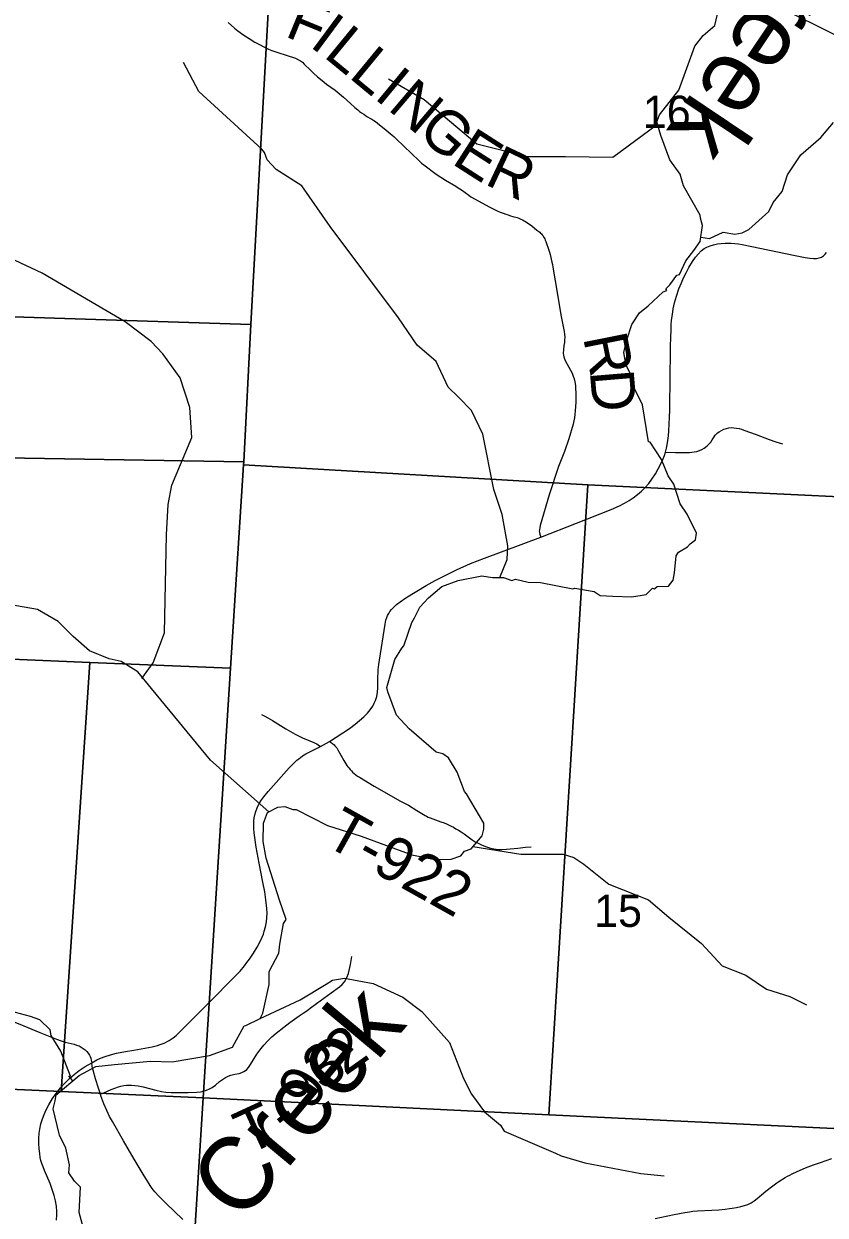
# Model space of a CAD drawing. Extents: x -2.1 to 31.9, y 6.3 to 28.3.
# Drawn here: x 2.076 to 3.117, y 21.978 to 23.525 of the extents above; entities that cross this region are included whole.
import ezdxf

# ---------------------------------------------------------------- set-up
doc = ezdxf.new("R2010")
doc.units = 0
for name, color, linetype in [('GM_X_County_Road', 7, 'Continuous'), ('GM_X_Minor_River', 7, 'Continuous'), ('GM_X_Minor_River_Text', 7, 'Continuous'), ('GM_X_Section', 7, 'Continuous'), ('GM_X_Section_Text', 7, 'Continuous'), ('GM_X_State_Route', 7, 'Continuous'), ('GM_X_Township_Road', 7, 'Continuous'), ('GM_X_Township_Road_Text', 7, 'Continuous'), ('TX_P_1', 7, 'Continuous')]:
    doc.layers.add(name, color=color, linetype=linetype)

msp = doc.modelspace()

# ---------------------------------------------------------------- linework, layer by layer
at = {"layer": 'GM_X_County_Road'}
for points in [[(2.0642, 22.2285), (2.0759, 22.2238), (2.0964, 22.2151), (2.1181, 22.2065), (2.1243, 22.2044), (2.1268, 22.2035), (2.1295, 22.2027), (2.1412, 22.1998), (2.1444, 22.1988), (2.1475, 22.1977), (2.1505, 22.1963), (2.1531, 22.1945), (2.1555, 22.1926), (2.1577, 22.1904), (2.1595, 22.1881), (2.1609, 22.1859), (2.1619, 22.184), (2.1627, 22.1818), (2.1634, 22.1794), (2.164, 22.1758)], [(2.8958, 21.9737), (2.9205, 21.9787), (2.9344, 21.9814), (2.9405, 21.9824), (2.9448, 21.9829), (2.9509, 21.9835), (2.9695, 21.9842), (2.9788, 21.9848), (2.9869, 21.9858), (2.9924, 21.9865), (2.9961, 21.987), (3.0018, 21.988), (3.0074, 21.989), (3.0122, 21.9903), (3.0163, 21.9919), (3.0208, 21.9941), (3.0246, 21.9964), (3.0286, 21.9994), (3.0398, 22.0091), (3.0471, 22.0149), (3.0541, 22.0198), (3.0566, 22.0215), (3.0649, 22.0266), (3.0681, 22.0284), (3.0708, 22.0298), (3.074, 22.0314), (3.0806, 22.0348), (3.0914, 22.0394), (3.1018, 22.0433), (3.1106, 22.0464), (3.1254, 22.0513)]]:
    msp.add_lwpolyline(points, dxfattribs=at)
at = {"layer": 'GM_X_Minor_River'}
for points in [[(2.8588, 23.1122), (2.8592, 23.1149), (2.8656, 23.1347), (2.8758, 23.1499), (2.8867, 23.1591), (2.9064, 23.1773), (2.9113, 23.1789), (2.9098, 23.1812), (2.9151, 23.1861), (2.9241, 23.199), (2.9275, 23.1998), (2.9358, 23.2173), (2.9464, 23.231), (2.9543, 23.2424), (2.9577, 23.2634), (2.955, 23.2728), (2.9543, 23.2766), (2.9327, 23.315), (2.9285, 23.3302), (2.9149, 23.3488), (2.9032, 23.3803), (2.8982, 23.3981), (2.9016, 23.4069), (2.9269, 23.4392), (2.9477, 23.4963), (2.9582, 23.51), (2.9737, 23.5233), (2.9771, 23.5378)], [(2.6941, 22.8063), (2.7036, 22.8293), (2.7046, 22.8472), (2.6971, 22.888), (2.6864, 22.9206), (2.6723, 22.9925), (2.6574, 23.0229), (2.6405, 23.0402), (2.6269, 23.0535), (2.6117, 23.0867), (2.5866, 23.108), (2.5627, 23.1433), (2.4737, 23.2619), (2.4371, 23.3147), (2.4038, 23.3359), (2.3921, 23.3488), (2.3886, 23.358), (2.3849, 23.3627), (2.3033, 23.4374), (2.2833, 23.4749)], [(2.8992, 23.3946), (2.8408, 23.3516), (2.7796, 23.3524), (2.7301, 23.3525), (2.6645, 23.369), (2.5959, 23.4266), (2.5495, 23.4535)], [(2.2292, 22.675), (2.2438, 22.6952), (2.2584, 22.7344), (2.261, 22.8616), (2.2631, 22.9011), (2.2682, 22.9261), (2.294, 22.9878), (2.2915, 23.0269), (2.2788, 23.0655), (2.2562, 23.0966), (2.2413, 23.1128), (2.2074, 23.1381), (2.0996, 23.2016), (2.0573, 23.2215), (1.9474, 23.2691), (1.86, 23.3382), (1.844, 23.3483), (1.765, 23.3707), (1.749, 23.3785), (1.7173, 23.4027)], [(2.9553, 23.2483), (2.9664, 23.2463), (2.9842, 23.2547), (2.9993, 23.2521), (3.0091, 23.254), (3.0178, 23.2582), (3.0435, 23.2814), (3.0495, 23.2932), (3.0609, 23.3077), (3.068, 23.329), (3.0854, 23.3552), (3.1111, 23.3777), (3.1277, 23.3971)], [(2.5694, 22.7172), (2.5798, 22.7475), (2.5832, 22.7536), (2.5903, 22.7677), (2.6017, 22.7799), (2.6187, 22.7943), (2.6402, 22.8024), (2.6708, 22.8081), (2.6848, 22.8063), (2.6988, 22.8063), (2.7098, 22.8022), (2.7147, 22.8041), (2.7309, 22.7999), (2.7472, 22.7996), (2.7892, 22.7913), (2.7918, 22.7921), (2.8168, 22.788), (2.8247, 22.7827), (2.841, 22.7819), (2.8659, 22.7809), (2.8844, 22.7839), (2.8927, 22.7923), (2.895, 22.7916), (2.8988, 22.7946), (2.9135, 22.7947), (2.9192, 22.8027), (2.9211, 22.8122), (2.9233, 22.8342), (2.9263, 22.8392), (2.938, 22.846), (2.9414, 22.8498), (2.9482, 22.8552), (2.9497, 22.8639), (2.9376, 22.8882), (2.9285, 22.9019), (2.9202, 22.9273), (2.913, 22.9383), (2.9043, 22.9592), (2.8895, 22.982), (2.8873, 22.9823), (2.8797, 23.0302), (2.8649, 23.0602), (2.863, 23.072), (2.8577, 23.083), (2.8554, 23.0986), (2.8588, 23.1122)], [(2.3942, 22.5017), (2.3181, 22.569), (2.2416, 22.6621), (2.2241, 22.6836), (2.2022, 22.6972), (2.1868, 22.7003), (2.161, 22.711), (2.1401, 22.7295), (2.1206, 22.7488), (2.0935, 22.7644), (2.0465, 22.7727)], [(2.347, 22.1959), (2.3621, 22.2236), (2.3644, 22.2244), (2.3829, 22.2332), (2.3863, 22.2404), (2.3946, 22.2777), (2.3946, 22.2944), (2.407, 22.3184), (2.4085, 22.3298), (2.413, 22.3568), (2.4164, 22.3621), (2.4081, 22.3872), (2.3907, 22.4415), (2.3869, 22.4631), (2.3872, 22.4871), (2.3925, 22.5008), (2.4057, 22.508), (2.4148, 22.5088), (2.4254, 22.505), (2.4295, 22.505), (2.4704, 22.4842), (2.5142, 22.4703), (2.58, 22.4461), (2.6099, 22.4397), (2.6311, 22.4402), (2.6436, 22.4444), (2.6481, 22.4508), (2.6568, 22.4535), (2.6711, 22.4707), (2.6734, 22.4794), (2.6734, 22.487), (2.6507, 22.525), (2.6484, 22.528), (2.6389, 22.5534), (2.6276, 22.572), (2.62, 22.5773), (2.6117, 22.5792), (2.5765, 22.6095), (2.5598, 22.6274), (2.5489, 22.6577), (2.5473, 22.6634), (2.5579, 22.6996), (2.567, 22.7144), (2.5694, 22.7172)], [(2.6593, 22.4566), (2.7215, 22.4468), (2.7763, 22.4466), (2.7905, 22.4423), (2.8035, 22.4336), (2.8356, 22.4079), (2.8872, 22.3876), (2.9137, 22.3651), (2.9561, 22.3307), (2.9832, 22.3018), (3.0138, 22.2898), (3.0405, 22.2715), (3.0708, 22.2621), (3.0928, 22.2512)], [(2.3829, 22.2332), (2.4346, 22.2577), (2.4684, 22.2779), (2.4769, 22.283), (2.4925, 22.2859), (2.5297, 22.279), (2.5681, 22.2611), (2.5928, 22.2424), (2.629, 22.2022), (2.6469, 22.1553), (2.6576, 22.1352), (2.6743, 22.1119), (2.695, 22.0949), (2.7, 22.0872), (2.7664, 22.0585), (2.7739, 22.0548), (2.8046, 22.0459), (2.8775, 22.0318), (2.9077, 22.0288)], [(2.1395, 22.1522), (2.1343, 22.1584), (2.1365, 22.1584), (2.124, 22.1907), (2.1115, 22.2112), (2.11, 22.2184), (2.0964, 22.2317), (2.0843, 22.2358), (2.0385, 22.2479)], [(2.1694, 22.1711), (2.1936, 22.1734), (2.2405, 22.1781), (2.2684, 22.177), (2.3168, 22.1851), (2.347, 22.1959)], [(2.1541, 21.9574), (2.1476, 21.9814), (2.1495, 22.0144), (2.1416, 22.022), (2.1344, 22.033), (2.1351, 22.0433), (2.1302, 22.0649), (2.1222, 22.0816), (2.1215, 22.0835), (2.1139, 22.1162), (2.1165, 22.1265), (2.1176, 22.1341), (2.1479, 22.1592), (2.1694, 22.1711)]]:
    msp.add_lwpolyline(points, dxfattribs=at)
at = {"layer": 'GM_X_Section'}
for points in [[(2.4194, 23.947), (3.4671, 23.8965), (3.4412, 23.4777), (3.416, 23.0562), (3.4084, 22.8979), (2.8085, 22.9264), (2.3612, 22.9526), (2.3614, 22.9562), (2.3709, 23.1348), (2.3938, 23.5483)], [(1.3641, 23.5904), (2.3938, 23.5483), (2.3709, 23.1348), (1.3376, 23.1681)], [(1.3376, 23.1681), (2.3709, 23.1348), (2.3614, 22.9562), (1.3254, 22.9735)], [(2.3614, 22.9562), (2.3612, 22.9526), (2.3441, 22.6882), (2.1616, 22.6959), (1.3796, 22.7292), (1.3102, 22.7307), (1.3254, 22.9735)], [(2.8085, 22.9264), (2.758, 22.1083), (2.3089, 22.1301), (2.3441, 22.6882), (2.3612, 22.9526)], [(3.4084, 22.8979), (3.3918, 22.6602), (3.3206, 22.6609), (3.2816, 22.083), (2.758, 22.1083), (2.8085, 22.9264)], [(2.1616, 22.6959), (2.1245, 22.1384), (1.3414, 22.174), (1.3796, 22.7292)], [(2.3441, 22.6882), (2.3089, 22.1301), (2.1245, 22.1384), (2.1616, 22.6959)], [(1.3414, 22.174), (2.1245, 22.1384), (2.3089, 22.1301), (2.2923, 21.8673), (1.3233, 21.9111)], [(2.3089, 22.1301), (2.758, 22.1083), (3.2816, 22.083), (3.264, 21.8222), (2.2923, 21.8673)]]:
    msp.add_lwpolyline(points, close=True, dxfattribs=at)
at = {"layer": 'GM_X_State_Route'}
for points in [[(2.2187, 22.1924), (2.2427, 22.1966), (2.2494, 22.1983), (2.253, 22.1994), (2.2582, 22.2015), (2.2644, 22.2046), (2.2697, 22.2081), (2.2736, 22.2112), (2.2791, 22.2163), (2.3187, 22.2563), (2.3474, 22.2852), (2.3524, 22.2903), (2.3569, 22.295), (2.3625, 22.3018), (2.3657, 22.306), (2.3688, 22.3103), (2.3741, 22.318), (2.379, 22.326), (2.3826, 22.3326), (2.3855, 22.3389), (2.387, 22.343), (2.3882, 22.3466), (2.3898, 22.3526), (2.391, 22.3588), (2.3916, 22.3644), (2.3918, 22.3701), (2.3915, 22.3764), (2.3903, 22.3875), (2.3889, 22.398), (2.3864, 22.4102), (2.3816, 22.435), (2.3778, 22.4558), (2.3768, 22.4621), (2.3758, 22.4684), (2.3751, 22.4746), (2.3748, 22.4795), (2.3745, 22.485), (2.3746, 22.4899), (2.3749, 22.494), (2.3758, 22.498), (2.3772, 22.5024), (2.3791, 22.507), (2.3813, 22.5116), (2.3839, 22.5159), (2.3878, 22.5214), (2.3932, 22.5281), (2.4206, 22.5589), (2.4243, 22.5628), (2.4278, 22.5663), (2.4305, 22.5688), (2.4329, 22.5708), (2.4352, 22.5725), (2.4379, 22.5744), (2.44, 22.5758), (2.4422, 22.577), (2.4446, 22.5783), (2.4472, 22.5796), (2.4613, 22.5867), (2.4731, 22.5932), (2.4988, 22.6101), (2.5061, 22.6155), (2.5121, 22.6204), (2.5175, 22.6252), (2.5222, 22.63), (2.5258, 22.6342), (2.529, 22.6389), (2.5311, 22.6428), (2.5326, 22.6462), (2.5342, 22.6517), (2.5351, 22.6572), (2.5355, 22.6628), (2.5359, 22.6777), (2.5361, 22.682), (2.5363, 22.6863), (2.5369, 22.6931), (2.5377, 22.6986), (2.5454, 22.7457), (2.5463, 22.7505), (2.5472, 22.754), (2.5483, 22.7568), (2.5498, 22.7595), (2.5514, 22.7619), (2.5536, 22.7644), (2.556, 22.7671), (2.56, 22.7709), (2.5648, 22.7747), (2.572, 22.7796), (2.5984, 22.7958), (2.6103, 22.8024), (2.6247, 22.8097), (2.6381, 22.8161), (2.6563, 22.8242), (2.6741, 22.8313), (2.7474, 22.8584), (2.7937, 22.8767), (2.8387, 22.8946), (2.8496, 22.8994), (2.8563, 22.9028), (2.8622, 22.9062), (2.8674, 22.9097), (2.8729, 22.9139), (2.8782, 22.9183), (2.8831, 22.9232), (2.8876, 22.9284), (2.8918, 22.9339), (2.8963, 22.9407), (2.9, 22.9472), (2.9034, 22.9539), (2.906, 22.9596), (2.908, 22.9647), (2.9093, 22.9689), (2.9107, 22.9742), (2.9116, 22.9785), (2.9126, 22.9842), (2.9133, 22.9903), (2.9138, 22.9965), (2.9144, 23.0055), (2.9148, 23.0148), (2.915, 23.0232), (2.9152, 23.0338), (2.9154, 23.0588), (2.9159, 23.1068), (2.9162, 23.1178), (2.9166, 23.1277), (2.9169, 23.1344), (2.9174, 23.1405), (2.9184, 23.1477), (2.9195, 23.1553), (2.9212, 23.1631), (2.9236, 23.1716), (2.9268, 23.1809), (2.93, 23.189), (2.9328, 23.1954), (2.9361, 23.2019), (2.9396, 23.2086), (2.9444, 23.2164), (2.9486, 23.2223), (2.952, 23.2263), (2.9559, 23.2303), (2.9598, 23.2333), (2.9633, 23.2354), (2.9673, 23.237), (2.9719, 23.2383), (2.9768, 23.2394), (2.9816, 23.2401), (2.987, 23.2405), (2.9905, 23.2406), (2.9947, 23.2405), (2.9994, 23.24), (3.0042, 23.2394), (3.0091, 23.2386), (3.078, 23.2243), (3.0907, 23.2217), (3.097, 23.2207), (3.1016, 23.2203), (3.1055, 23.2205), (3.1089, 23.2212), (3.1119, 23.2223), (3.1146, 23.224), (3.1168, 23.2262), (3.1184, 23.2282)], [(2.164, 22.1758), (2.1706, 22.1796), (2.1756, 22.1819), (2.1814, 22.184), (2.1885, 22.1861), (2.1962, 22.1881), (2.2078, 22.1905), (2.2187, 22.1924)], [(2.1183, 21.9713), (2.1187, 21.9782), (2.1186, 21.9826), (2.1181, 21.9894), (2.117, 21.9963), (2.1152, 22.0036), (2.1127, 22.0113), (2.1098, 22.0189), (2.1026, 22.0361), (2.1008, 22.0408), (2.0992, 22.0449), (2.0979, 22.0491), (2.0971, 22.0529), (2.0964, 22.0579), (2.0957, 22.0641), (2.0952, 22.0708), (2.0953, 22.0776), (2.0958, 22.0844), (2.0965, 22.0898), (2.098, 22.0965), (2.0999, 22.1029), (2.1021, 22.1087), (2.1048, 22.1149), (2.1083, 22.1214), (2.1132, 22.1293), (2.1179, 22.136), (2.1236, 22.1433), (2.1292, 22.1495), (2.1353, 22.1555), (2.1412, 22.1607), (2.1479, 22.1657), (2.1557, 22.1709), (2.164, 22.1758)], [(2.2321, 22.0291), (2.219, 22.0508), (2.2055, 22.0743), (2.1909, 22.0996), (2.1873, 22.106), (2.1835, 22.1138), (2.1798, 22.1223), (2.1759, 22.1327), (2.1752, 22.1349), (2.1727, 22.1427), (2.1691, 22.1548), (2.1658, 22.1663), (2.1651, 22.1689), (2.1646, 22.1713), (2.164, 22.1758)], [(2.2824, 21.9724), (2.2603, 21.9933), (2.2514, 22.0025), (2.246, 22.0084), (2.2427, 22.0126), (2.2401, 22.0163), (2.2351, 22.0241), (2.2321, 22.0291)]]:
    msp.add_lwpolyline(points, dxfattribs=at)
at = {"layer": 'GM_X_Township_Road'}
for points in [[(2.3411, 23.5269), (2.3494, 23.5197), (2.3537, 23.5163), (2.3618, 23.5105), (2.3687, 23.5061), (2.3759, 23.5016), (2.3938, 23.4925), (2.3978, 23.4907), (2.4019, 23.4892), (2.4206, 23.4834), (2.425, 23.4819), (2.4287, 23.4805), (2.4326, 23.4786), (2.4353, 23.4771), (2.4377, 23.4753), (2.4402, 23.4731), (2.4482, 23.4649), (2.4522, 23.4613), (2.4575, 23.4565), (2.4635, 23.4516), (2.4691, 23.4471), (2.4804, 23.439), (2.4911, 23.4302), (2.5, 23.4217), (2.506, 23.4164), (2.5096, 23.4134), (2.512, 23.4116), (2.5146, 23.4097), (2.5173, 23.4078), (2.5197, 23.4062), (2.5222, 23.4046), (2.5252, 23.4028), (2.5279, 23.4014), (2.5304, 23.3999), (2.5326, 23.3984), (2.5353, 23.3963), (2.5467, 23.387), (2.5542, 23.3808), (2.5565, 23.3788), (2.5594, 23.3761), (2.5893, 23.3472), (2.5907, 23.3459), (2.5925, 23.3444), (2.5954, 23.342), (2.6116, 23.3302), (2.6236, 23.3223), (2.637, 23.3143), (2.6402, 23.3124), (2.6422, 23.3111), (2.6446, 23.3095), (2.6538, 23.3026), (2.6567, 23.3007), (2.6814, 23.287), (2.6856, 23.2849), (2.6906, 23.2825), (2.6948, 23.2808), (2.6985, 23.2793), (2.7019, 23.2782), (2.7049, 23.2771), (2.7082, 23.2761), (2.7111, 23.2752), (2.7166, 23.2736), (2.7189, 23.2728), (2.7213, 23.2717), (2.7238, 23.2706), (2.7287, 23.2678), (2.7356, 23.2628), (2.7424, 23.2574), (2.746, 23.2545), (2.7472, 23.2535), (2.7482, 23.2525), (2.7492, 23.2514), (2.75, 23.2502), (2.7519, 23.2472), (2.7526, 23.2459), (2.7533, 23.2444), (2.754, 23.2426), (2.7578, 23.2314), (2.7586, 23.2286), (2.7594, 23.2257), (2.7619, 23.2156), (2.7626, 23.2125), (2.7631, 23.2094), (2.769, 23.1737), (2.7733, 23.1472), (2.7777, 23.1258), (2.7782, 23.1221), (2.7785, 23.1184), (2.7784, 23.1148), (2.778, 23.1112), (2.7773, 23.1073), (2.7767, 23.1018), (2.7766, 23.0974), (2.7767, 23.0951), (2.7773, 23.0928), (2.7782, 23.0902), (2.7797, 23.0873), (2.786, 23.0756), (2.7881, 23.0715), (2.7895, 23.0678), (2.7908, 23.0641), (2.7917, 23.0601), (2.7923, 23.0555), (2.7927, 23.0514), (2.793, 23.0466), (2.7931, 23.0402), (2.7929, 23.0338), (2.7922, 23.0228), (2.7918, 23.0184), (2.791, 23.0137), (2.7903, 23.0096), (2.7893, 23.0053), (2.784, 22.9862), (2.7781, 22.9696), (2.7706, 22.9502), (2.7583, 22.9135), (2.7468, 22.8737), (2.746, 22.8705), (2.7456, 22.8682), (2.7455, 22.8665), (2.7456, 22.8647), (2.7462, 22.8625), (2.7474, 22.8584)], [(2.9093, 22.9689), (2.9224, 22.9683), (2.937, 22.9685), (2.9408, 22.9686), (2.9438, 22.9689), (2.9467, 22.9693), (2.9501, 22.97), (2.9535, 22.9711), (2.9566, 22.9724), (2.9596, 22.974), (2.9616, 22.9755), (2.9637, 22.9773), (2.9663, 22.9798), (2.9682, 22.982), (2.9702, 22.985), (2.9726, 22.9888), (2.9739, 22.9908), (2.9752, 22.9925), (2.9769, 22.994), (2.979, 22.9955), (2.982, 22.9972), (2.9854, 22.9987), (2.9888, 22.9998), (2.9917, 23.0004), (2.9951, 23.0008), (2.9982, 23.0007), (3.0016, 23.0003), (3.0051, 22.9996), (3.0081, 22.9987), (3.0111, 22.9976), (3.0272, 22.9917), (3.0441, 22.9852), (3.0528, 22.9823), (3.0616, 22.9797)], [(2.3844, 22.6283), (2.3889, 22.6259), (2.3928, 22.6239), (2.3987, 22.6204), (2.416, 22.6094), (2.4284, 22.6027), (2.4378, 22.598), (2.4525, 22.5919), (2.4544, 22.5911), (2.4565, 22.59), (2.4582, 22.5888), (2.4613, 22.5867)], [(2.4731, 22.5932), (2.4766, 22.5906), (2.4788, 22.5888), (2.48, 22.5876), (2.4812, 22.5863), (2.4824, 22.5847), (2.4839, 22.5821), (2.4915, 22.5684), (2.4941, 22.5642), (2.4955, 22.5621), (2.4968, 22.5604), (2.4979, 22.5589), (2.4996, 22.5568), (2.5014, 22.5549), (2.503, 22.5532), (2.505, 22.5516), (2.507, 22.55), (2.5092, 22.5483), (2.5119, 22.5466), (2.531, 22.5349), (2.565, 22.5156), (2.5754, 22.5104), (2.5864, 22.5035), (2.5972, 22.497), (2.5991, 22.496), (2.6011, 22.4949), (2.6035, 22.4939), (2.6175, 22.4889), (2.6217, 22.4873), (2.6248, 22.4861), (2.6285, 22.4845), (2.6311, 22.4831), (2.634, 22.4817), (2.6371, 22.4799), (2.6404, 22.478), (2.6439, 22.4757), (2.6477, 22.473), (2.6583, 22.4655), (2.6623, 22.463), (2.6667, 22.4606), (2.6714, 22.4584), (2.6767, 22.4563), (2.6821, 22.4547), (2.6863, 22.4536), (2.6894, 22.4531), (2.6923, 22.4529), (2.6968, 22.4528), (2.7028, 22.4531), (2.7176, 22.4547), (2.7276, 22.4557), (2.7348, 22.4564)], [(2.1752, 22.1349), (2.1797, 22.1368), (2.1893, 22.1409), (2.1987, 22.1445), (2.202, 22.1454), (2.2056, 22.1462), (2.209, 22.1467), (2.2123, 22.1469), (2.2157, 22.1468), (2.2199, 22.1464), (2.2245, 22.1458), (2.2307, 22.1445), (2.2475, 22.1401), (2.2548, 22.1386), (2.2603, 22.1378), (2.267, 22.1374), (2.2745, 22.1372), (2.2894, 22.1374), (2.3005, 22.1378), (2.3054, 22.1382), (2.309, 22.1389), (2.3132, 22.1402), (2.3172, 22.1419), (2.3203, 22.1437), (2.3247, 22.1469), (2.33, 22.1513), (2.334, 22.1543), (2.3377, 22.1566), (2.3411, 22.1583), (2.3446, 22.1596), (2.3501, 22.1609), (2.3555, 22.162), (2.359, 22.1631), (2.3617, 22.1644), (2.3638, 22.1657), (2.3656, 22.1673), (2.3676, 22.1695), (2.3704, 22.1736), (2.3785, 22.1868), (2.3825, 22.1924), (2.3875, 22.1987), (2.3926, 22.2043), (2.398, 22.2095), (2.4036, 22.2144), (2.4134, 22.2221), (2.4213, 22.2281), (2.4335, 22.2366), (2.4386, 22.2401), (2.4421, 22.2426), (2.4457, 22.2451), (2.4477, 22.2466), (2.4562, 22.2528), (2.4752, 22.2668), (2.4857, 22.2745), (2.4895, 22.2777), (2.4924, 22.2808), (2.4943, 22.2839), (2.4956, 22.2866), (2.4974, 22.2919), (2.5, 22.3033), (2.5012, 22.3087), (2.5021, 22.3139)]]:
    msp.add_lwpolyline(points, dxfattribs=at)
at = {"layer": 'TX_P_1'}
msp.add_lwpolyline([(2.6072, 24.0345), (3.2845, 23.4344), (2.6072, 23.7698)], close=True, dxfattribs=at)

# ---------------------------------------------------------------- texts
at = {"layer": 'GM_X_Minor_River_Text'}
for height, rotation, p in [(0.09469, 236.1304, (3.0983, 23.6674)), (0.0947, 50.1344, (2.3579, 21.9654))]:
    msp.add_text('Creek', height=height, rotation=rotation, dxfattribs=at).set_placement(p)
at = {"layer": 'GM_X_Section_Text'}
for s, p in [('16', (2.8799, 23.3901)), ('15', (2.8166, 22.3523))]:
    msp.add_text(s, height=0.04186, rotation=0, dxfattribs=at).set_placement(p)
at = {"layer": 'GM_X_Township_Road_Text'}
for s, height, rotation, p in [('F', 0.0568, 337.6802, (2.4134, 23.5096)), ('I', 0.0568, 323.4986, (2.4456, 23.4968)), ('L', 0.0568, 320.6334, (2.4638, 23.4834)), ('L', 0.0568, 320.4721, (2.4966, 23.4565)), ('I', 0.0568, 320.4393, (2.5294, 23.4294)), ('N', 0.0568, 319.5629, (2.5472, 23.4147)), ('G', 0.0568, 319.276, (2.5852, 23.3823)), ('E', 0.0568, 327.3764, (2.6301, 23.3445)), ('R', 0.0568, 334.7222, (2.6729, 23.3177)), ('R', 0.0568, 281.2384, (2.8022, 23.118)), ('D', 0.0568, 274.719, (2.8111, 23.074)), ('T-922', 0.05682, 330.8119, (2.4637, 22.4604)), ('2', 0.0568, 35.3991, (2.4931, 22.1581)), ('3', 0.0568, 36.3172, (2.4651, 22.1375)), ('9', 0.0568, 58.8682, (2.4509, 22.1119)), ('T', 0.0568, 24.7018, (2.3667, 22.0556)), ('-', 0.0568, 37.6277, (2.4172, 22.0806))]:
    msp.add_text(s, height=height, rotation=rotation, dxfattribs=at).set_placement(p)

doc.saveas('drawing.dxf')
